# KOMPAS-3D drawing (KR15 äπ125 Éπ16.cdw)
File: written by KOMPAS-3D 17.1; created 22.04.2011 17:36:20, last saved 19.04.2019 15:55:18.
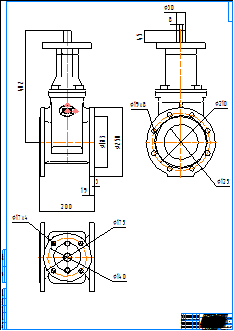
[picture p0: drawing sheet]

Title block, sheet 1: name: KR15 Ду125 Ру16; material: Внимание! Данный продукт является объектом авторского права ООО «Торговый Дом АДЛ». / Запрещается изменение, копирование, распространение / (в том числе путем копирования на другие сайты и ресурсы в Интернете) / или любое иное использование информации и объектов без предварительного / согласия правообладателя (ООО «Торговый Дом АДЛ»).; scale: 1:1; sheets: 1; organisation: ООО "Торговый дом АДЛ"; sheet format: A0; stored path: \\adlc.lan\data\АДЛ_ПКД\3D-модели\ADL production\Клиновые задвижки серии KR ГРАНАР\Клиновые задвижки KR15\С голым штоком\KOMPAS 2D\KR15 Ду125 Ру16.cdw

Views: Спереди 4, Проекционный вид 5, Проекционный вид 6
Dimensions and other numbers on the sheet: 250; 183; 402; 3; 19; 200; 175; 17; 140; 8; 30; 45; 210; 125; 1:1; 1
